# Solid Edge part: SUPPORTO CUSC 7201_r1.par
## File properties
Subject: SUPPORTO CUSC 7201
Author: f_grande
Template: Normal.par
Last saved by: f_grande
Revision: 18
Application: Solid Edge
Densità: 2712,000 kg/m^3
Precisione: 0,990
Tipo di contenuto documento: 0
Document Number: KR0131
Material: Alluminio, 1060
Stile della faccia: Alluminio
Stile di riempimento: ANSI38(Alluminio)
Stile virtuale: Alluminio lucidato
Coef. of Thermal Exp: 0.0
Thermal Conductivity: 221.0
Specific Heat: 920.0
Modulus of Elasticity: 68947570000.0
Poisson's Ratio: 0.33
Yield Stress: 27579028.0
Ultimate Stress: 68947570.0
Elongation: 0.0
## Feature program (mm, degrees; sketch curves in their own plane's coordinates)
sketch for "unnamed Protrusion 1" plane through (0, 0, 0) normal (0, -1, 0) x-axis (1, 0, 0)
  line (-35.0443, 29.8388) -> (24.9557, 29.8388)
  line (24.9557, 29.8388) -> (24.9557, -30.1612)
  line (24.9557, -30.1612) -> (-35.0443, -30.1612)
  line (-35.0443, -30.1612) -> (-35.0443, 29.8388)
  dimension (linear) = 35.0443
  dimension (linear) = 35.0443
extrude "unnamed Protrusion 1" add finite 20 along -normal
sketch for "Foro_6" plane through (-7.5443, -3, 2.3388) normal (0, -1, 0) x-axis (1, 0, 0)
hole "Foro_6" diameter 32.05 through
sketch for "Foro_7" plane through (-7.5443, 20, 2.3388) normal (0, 1, 0) x-axis (-1, 0, 0)
hole "Foro_7" diameter 4.5 through  CounterBoreDepth = 5 mm
sketch for "unnamed Hole 1" plane through (-7.5443, 20, 2.3388) normal (0, 1, 0) x-axis (-1, 0, 0)
  hole centre (21.07, 21.07) bore radius 2.25
hole "unnamed Hole 1" through
sketch for "unnamed Hole 2" plane through (-7.5443, 20, 2.3388) normal (0, 1, 0) x-axis (-1, 0, 0)
  hole centre (21.07, -26.07) bore radius 2.25
hole "unnamed Hole 2" through
sketch for "unnamed Hole 3" plane through (-7.5443, 20, 2.3388) normal (0, 1, 0) x-axis (-1, 0, 0)
hole "unnamed Hole 3" through
sketch for "Foro_11" plane through (-5.0443, 0, -0.1612) normal (0, -1, 0) x-axis (1, 0, 0)
  hole centre (23.57, 0) bore radius 1.621
hole "Foro_11" nominal diameter 4 through
sketch for "unnamed Hole 4" plane through (-5.0443, 0, -0.1612) normal (0, -1, 0) x-axis (1, 0, 0)
  hole centre (0, -23.57) bore radius 1.621
hole "unnamed Hole 4" through
sketch for "unnamed Hole 5" plane through (-5.0443, 0, -0.1612) normal (0, -1, 0) x-axis (1, 0, 0)
  hole centre (-23.57, 0) bore radius 1.621
hole "unnamed Hole 5" through
sketch for "unnamed Hole 6" plane through (-5.0443, 0, -0.1612) normal (0, -1, 0) x-axis (1, 0, 0)
hole "unnamed Hole 6" through
pattern "unnamed Pattern 1" of "Foro_7", "unnamed Hole 1", "unnamed Hole 2", "unnamed Hole 3"
pattern "unnamed Pattern 2" of "Foro_11", "unnamed Hole 4", "unnamed Hole 5", "unnamed Hole 6"
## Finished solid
Body 1: solid body, 23 faces, 38 edges, 8 vertices.
  Faces by surface: cylinder 13, plane 10
  Edges by curve: circle 26, line 12
Bounding box of the edges (mm): 60.000 x 20.000 x 60.000, from (-35.0443, 0, -30.1612) to (24.9557, 20, 29.8388).
Cylindrical faces by radius (mm): R1.621 x4, R2.25 x4, R4 x4, R16.025 x1
Planar faces by outward normal: +x 1, +y 5, +z 1, -x 1, -y 1, -z 1
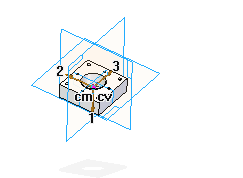
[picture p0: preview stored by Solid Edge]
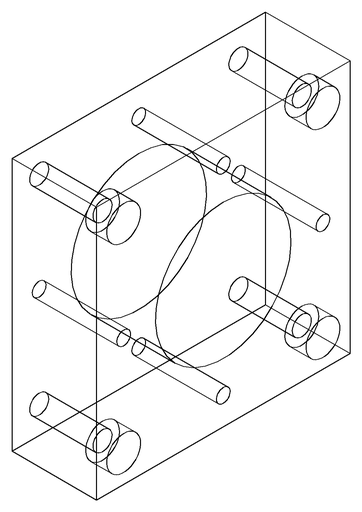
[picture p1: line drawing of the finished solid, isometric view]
